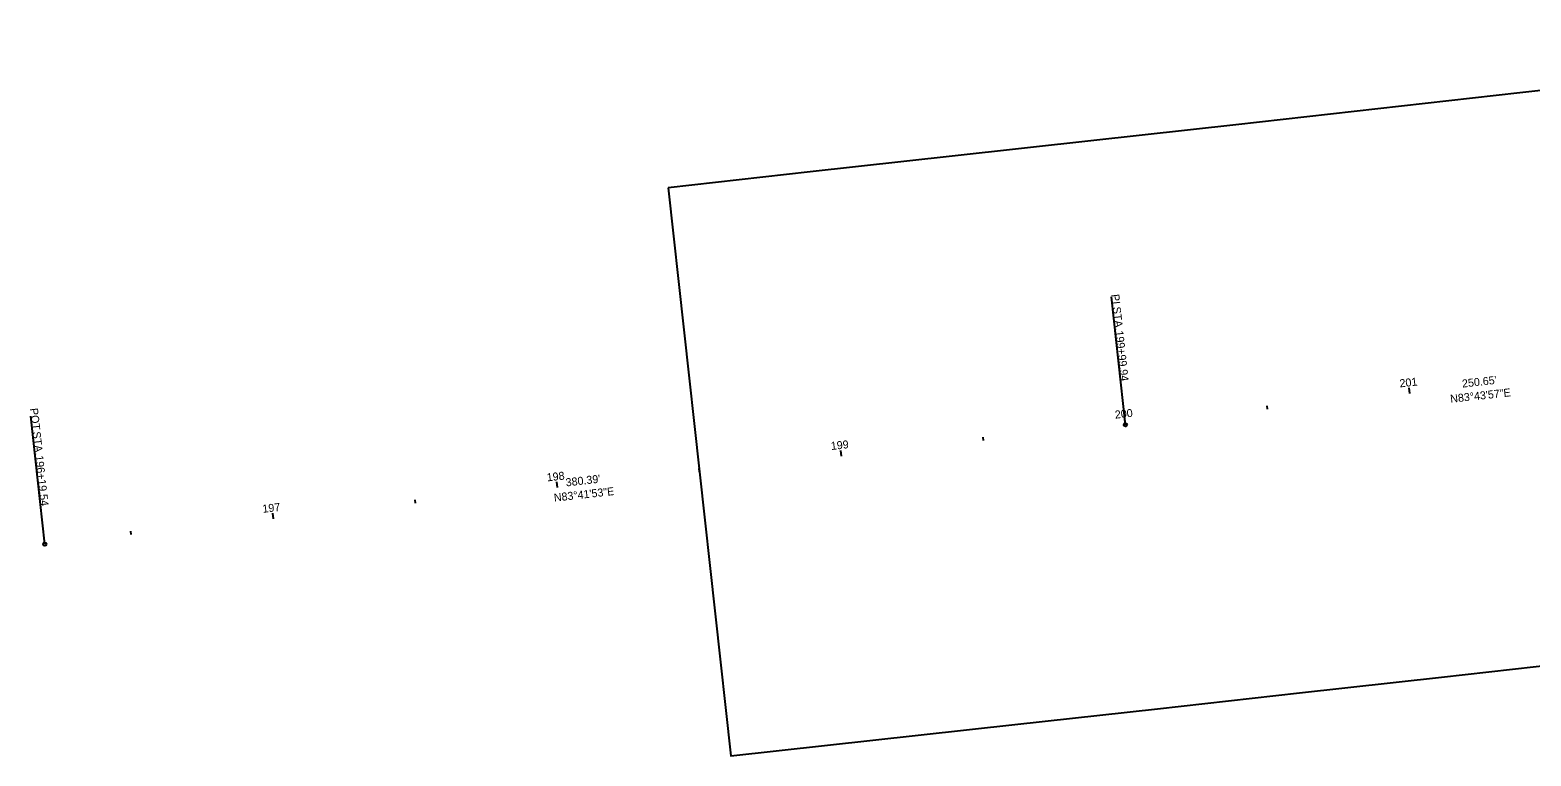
# Model space of a CAD drawing. Extents: x 1600023 to 1602105, y 286460 to 286887.
# Drawn here: x 1600023 to 1600548, y 286460 to 286714 of the extents above; entities that cross this region are included whole.
import ezdxf

# ---------------------------------------------------------------- set-up
doc = ezdxf.new("R2010")
doc.units = 0
for name, color, linetype in [('DT_X_Contour_Minor', 7, 'Continuous'), ('DT_X_Island', 7, 'Continuous'), ('DT_X_Void', 7, 'Continuous'), ('SC_Scratch3', 7, 'Continuous'), ('UT_X_Overhead_Electric', 7, 'Continuous')]:
    doc.layers.add(name, color=color, linetype=linetype)

msp = doc.modelspace()

# ---------------------------------------------------------------- linework, layer by layer
at = {"layer": 'DT_X_Island'}
for p, q in [((1600406.13, 286576.06), (1600401.22, 286620.8)), ((1600028.03, 286534.31), (1600023.1, 286579.04))]:
    msp.add_line(p, q, dxfattribs=at)
for centre in [(1600406.13, 286576.06), (1600028.03, 286534.31)]:
    msp.add_circle(centre, 0.6, dxfattribs=at)
at = {"layer": 'SC_Scratch3'}
for p, q in [((1600505.59, 286586.99), (1600505.38, 286588.98)), ((1600455.89, 286581.53), (1600455.76, 286582.72)), ((1600406.19, 286576.07), (1600405.97, 286578.06)), ((1600356.49, 286570.58), (1600356.36, 286571.78)), ((1600306.8, 286565.1), (1600306.58, 286567.08)), ((1600257.1, 286559.61), (1600256.97, 286560.8)), ((1600207.4, 286554.12), (1600207.18, 286556.11)), ((1600157.7, 286548.63), (1600157.57, 286549.82)), ((1600108.01, 286543.14), (1600107.79, 286545.13)), ((1600058.31, 286537.65), (1600058.18, 286538.85))]:
    msp.add_line(p, q, dxfattribs=at)
at = {"layer": 'UT_X_Overhead_Electric'}
msp.add_lwpolyline([(1600246.12, 286659), (1600268.07, 286460.21), (1600317.77, 286465.7), (1600367.47, 286471.18), (1600417.32, 286476.69), (1600467.01, 286482.25), (1600516.7, 286487.82), (1600566.39, 286493.38), (1600616.08, 286498.95), (1600665.77, 286504.51), (1600715.46, 286510.08), (1600770.49, 286516.91), (1600737.4, 286714.15), (1600693.2, 286708.83), (1600643.51, 286703.27), (1600593.82, 286697.7), (1600544.13, 286692.14), (1600494.44, 286686.57), (1600444.75, 286681.01), (1600395.06, 286675.45), (1600345.52, 286669.97), (1600295.82, 286664.49)], close=True, dxfattribs=at)

# ---------------------------------------------------------------- texts
at = {"layer": 'DT_X_Contour_Minor'}
for s, rotation, p in [("250.65'", 6.2675, (1600524.06, 286589.06)), ("380.39'", 6.3018, (1600210.44, 286554.5))]:
    msp.add_text(s, height=2.8, rotation=rotation, dxfattribs=at).set_placement(p)
at = {"layer": 'DT_X_Island'}
for s, rotation, p in [('PI', 276.2675, (1600401.17, 286621.61)), (' STA. ', 276.2675, (1600401.54, 286618.24)), ('199+99.94', 276.2675, (1600402.57, 286608.85)), ('POT', 276.3018, (1600022.84, 286581.75)), (' STA. ', 276.3018, (1600023.63, 286574.59)), ('196+19.54', 276.3018, (1600024.67, 286565.2))]:
    msp.add_text(s, height=2.8, rotation=rotation, dxfattribs=at).set_placement(p)
at = {"layer": 'DT_X_Void'}
for s, rotation, p in [('N83°43\'57"E', 6.2675, (1600519.93, 286583.73)), ('N83°41\'53"E', 6.3018, (1600206.31, 286549.17))]:
    msp.add_text(s, height=2.8, rotation=rotation, dxfattribs=at).set_placement(p)
at = {"layer": 'SC_Scratch3'}
for s, rotation, p in [('201', 6.2675, (1600502.19, 286589.13)), ('200', 6.2675, (1600402.59, 286578.19)), ('199', 6.3018, (1600303.22, 286567.22)), ('198', 6.3018, (1600203.81, 286556.24)), ('197', 6.3018, (1600104.34, 286545.25))]:
    msp.add_text(s, height=2.8, rotation=rotation, dxfattribs=at).set_placement(p)

doc.saveas('drawing.dxf')
